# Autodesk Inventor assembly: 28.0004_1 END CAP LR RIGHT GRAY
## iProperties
Created: 2007-04
Part Number: 28.0004_1 END CAP LR RIGHT GRAY
Document SubType Name: Assembly
Designer: Andy Moles
Author: Andy Moles
